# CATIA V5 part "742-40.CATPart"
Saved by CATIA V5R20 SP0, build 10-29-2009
Part number: 742-40
Bounding box of the stored display mesh (mm): x -33 to 33.5, y -32.999 to 32.999, z -37 to 71
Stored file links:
  C:\Users\Utente\Desktop\IO LAVORO\3D X SITO CF\X SITO\742\742-40.CATPart
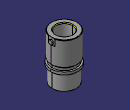
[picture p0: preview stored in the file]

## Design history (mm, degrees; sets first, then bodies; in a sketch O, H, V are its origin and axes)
Set1
  DatumSurface1 to DatumSurface38 "742-40"
Body1 (main body)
